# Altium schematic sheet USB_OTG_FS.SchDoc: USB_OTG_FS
size A4; Date: Not used; ApprovedBy: Not used; CheckedBy: Not used; Author: Not used; CompanyName: STMicroelectronics; DrawnBy: Not used; Engineer: Not used; Organization: Not used; Address1: Not used; Address2: Not used; Address3: Not used; Address4: Not used; Revision: Not used; SheetNumber: 5; SheetTotal: 8
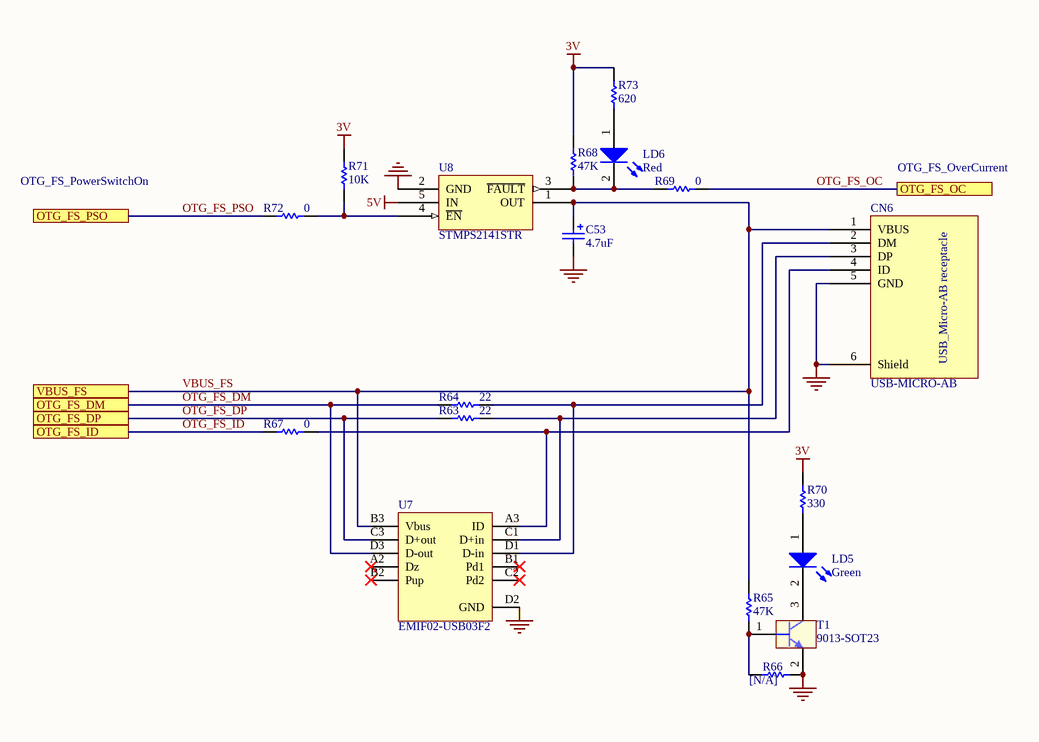
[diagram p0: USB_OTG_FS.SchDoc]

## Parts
C53  4.7uF  [TAN-A]
CN6  USB-MICRO-AB  [CON_USBMICROAB_MOLEX_47590-0001_H3]
LD5  Green  [0603D]
LD6  Red  [0603D]
R63  22  [0402R]
R64  22  [0402R]
R65  47K  [0402R]
R66  [N/A]  [0402R]
R67  0  [0402R]
R68  47K  [0402R]
R69  0  [0402R]
R70  330  [0603R]
R71  10K  [0402R]
R72  0  [0402R]
R73  620  [0603R]
T1  9013-SOT23  [SOT-23]
U7  EMIF02-USB03F2  [Flip Chip]
U8  STMPS2141STR  [SOT23-5L]

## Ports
OTG_FS_DM, OTG_FS_DP, OTG_FS_ID, OTG_FS_OC, OTG_FS_PSO, VBUS_FS

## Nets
3V: R68.2 R70.2 R71.2 R73.2
5V: U8.5(IN)
GND: C53.2 CN6.5(GND) CN6.6(Shield) R66.2 T1.2(E) U7.D2(GND) U8.2(GND)
OTG_FS_DM: R64.1 U7.D3(D-out) ; port OTG_FS_DM
OTG_FS_DP: R63.1 U7.C3(D+out) ; port OTG_FS_DP
OTG_FS_ID: R67.1 ; port OTG_FS_ID
OTG_FS_OC: R69.2 ; port OTG_FS_OC
OTG_FS_PSO: R72.1 ; port OTG_FS_PSO
VBUS_FS: C53.1 CN6.1(VBUS) R65.2 U7.B3(Vbus) U8.1(OUT) ; port VBUS_FS
NetCN6_2: CN6.2(DM) R64.2 U7.D1(D-in)
NetCN6_3: CN6.3(DP) R63.2 U7.C1(D+in)
NetCN6_4: CN6.4(ID) R67.2 U7.A3(ID)
NetLD5_1: LD5.1(A) R70.1
NetLD5_2: LD5.2(K) T1.3(C)
NetLD6_1: LD6.1(A) R73.1
NetLD6_2: LD6.2(K) R68.1 R69.1 U8.3(~{FAULT})
NetR65_1: R65.1 R66.1 T1.1(B)
NetR71_1: R71.1 R72.2 U8.4(~{EN})

Not connected (* = marked no-connect by the designer): U7 A2(Dz)* B1(Pd1)* B2(Pup)* C2(Pd2)*

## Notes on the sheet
- OTG_FS_PowerSwitchOn
- OTG_FS_OverCurrent

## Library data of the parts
C53 = Cap Pol1: Polarized Capacitor (Radial); Value: 47uF
CN6 = USB-MICRO-AB: USB-MICRO-AB, 47590-0001, SMT, MOLEX; Ref St: xxxxxxx
LD5 LD6 = LED2: Typical RED, GREEN, YELLOW, AMBER GaAs LED
R63-R65 R67-R70 R72 R73 = Resistor_ST: Resistor 0402 / 0603 / 0805; Value: 10K
R66 = Resistor_ST: Resistor 0402 / 0603 / 0805; Value: 10K; Fitted: NO
R71 = Resistor_ST: Resistor 0402 / 0603 / 0805
T1 = 9013-SOT23: NPN Bipolar Transistor
U7 = EMIF02-USB03F2: 2-line IPAD, EMI filter including ESD protection; Manuf_1: STM; Provided: ST; ECCN_US/EU: EAR99/NEC; Ref St: 9179037
U8 = STMPS2141STR: Enhanced single channel power switches; Manuf_1: STM; Provided: ST; ECCN_US/EU: EAR99/NEC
